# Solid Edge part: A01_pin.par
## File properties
Author: mokuno
Template: metric.par
Last saved by: edge
Revision: 32
Application: Solid Edge
Material: Copper
File Size: 0
Number of Sheets: 0
Number of Objects: 0
非切断部品: False
文書内容のタイプ: 0
Density: 8906
Accuracy: 0.99
Document Number: MP-101
Revision: 1
Project Name: Trolley Wheel Assembly
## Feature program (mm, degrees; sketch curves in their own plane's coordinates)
sketch for "unnamed RevolvedProtrusion 1" plane through (0, 0, 0) normal (0, -1, 0) x-axis (1, 0, 0)
  line (-194, 0) -> (-194, 10)
  line (-194, 10) -> (-12, 10)
  line (-12, 10) -> (-12, 18)
  line (-12, 18) -> (0, 18)
  line (0, 18) -> (0, 0)
  line (0, 0) -> (-194, 0)
  dimension (linear) = 12
  dimension (linear) = 194
  dimension (linear) = 194
revolve "unnamed RevolvedProtrusion 1" add full turn 360 deg
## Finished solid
Body 1: solid body, 5 faces, 4 edges, 0 vertices.
  Faces by surface: plane 3, cylinder 2
  Edges by curve: circle 4
Bounding box of the edges (mm): 194.000 x 36.000 x 36.000, from (-194, -18, -18) to (0, 18, 18).
Cylindrical faces by radius (mm): R10 x1, R18 x1
Planar faces by outward normal: +x 1, -x 2
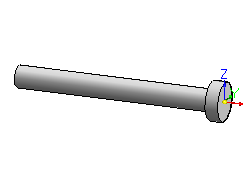
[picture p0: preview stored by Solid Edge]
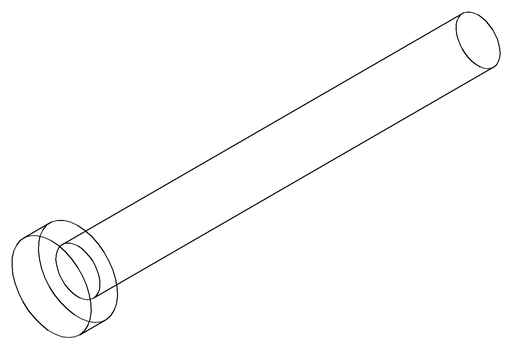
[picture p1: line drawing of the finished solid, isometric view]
